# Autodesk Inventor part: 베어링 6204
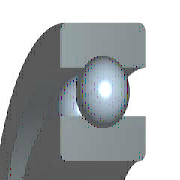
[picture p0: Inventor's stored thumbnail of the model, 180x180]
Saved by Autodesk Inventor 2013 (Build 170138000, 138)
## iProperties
IsCustomPart: 0
Created: 2009-02
Part Number: 베어링 6204
Material: 강, 연강
Description: 깊은 그루브 볼 베어링
Document SubType Name: Modeling
Standard: KS B 2023
Designer: KYOUNG IL JANG
Standards Organization: KS
Language: ko-KR
Size Designation: 6204 - 20 x 47 x 14
Categories: <MemberInstance><Categories><Category DisplayName="샤프트 부품" InternalName="7f7aeb1f-a693-4053-b835-cee3144e0d98" Mnemonic="SHFT"><Category DisplayName="베어링" Inter
Density: 7.86 g/cm^3
Mass: 104.255 g
Surface Area: 87.8912 cm^2
Volume: 13.264 cm^3
Author: KYOUNG IL JANG
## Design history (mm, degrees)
sketch "스케치" dims "d0" = 7.02 (= -0.26 x WD + 0.26 x BD)
  geometry: L1 (3.49, 16.75)-(10.51, 16.75); L2 (7, 16.75)-(7, 13.24); L3 (7, 16.75)-(7, 20.26); L4 (4.392, 14.401)-(0, 14.401); L5 (0, 10)-(14, 10); L6 (4.392, 19.099)-(0, 19.099); L7 (0, 23.5)-(14, 23.5); L8 (14, 10)-(14, 14.401); L9 (9.608, 14.401)-(14, 14.401); L10 (9.608, 19.099)-(14, 19.099); L11 (14, 23.5)-(14, 19.099); L12 (-1.4, 0)-(8.4, 0) reference; L13 (0, -0.3)-(0, 5.3) reference
  constraints: 22 end point, 4 point on line, 2 collinear, 2 perpendicular, 2 symmetric about line, 1 midpoint, 1 parallel, 14 other
  dimensions: "d9" = 20 diameter of L5 L12 (= WD); "d11" = 47 diameter of L7 L12 (= BD); "d12" = 14 distance between parallel lines of L8 L13 (= KB); "d13" = 28.802 diameter of L9 L12 (= 0.326 x BD + 0.674 x WD)
revolve "본체" stored, may be unused: angle "d6" = 90 deg
revolve "볼" stored, may be unused: angle "d7" = 90 deg
pattern_circular "IDS_ARRAYBALL[SIMPL:T]" dims angle "d3" = 360 deg
body "Solid1"
fillet "모깎기1" dims "d1" = 1 (= KRS)
other parameters: "WD" = 20 [user parameter; used in 5 equation terms], "BD" = 47 [user parameter; used in 5 equation terms], "KB" = 14 [user parameter; used in 1 equation term], "KRS" = 1 [user parameter; used in 1 equation term], "d4" = 0, "d5" = 0, "d8" = 0, "d14" = 0, "d15" = 0, "BBA" = 0 [user parameter], "BC0" = 6550000 [user parameter], "BC" = 1.27e+07 [user parameter], "BR" = 23.5 (= 0.5 x BD) [user parameter]
